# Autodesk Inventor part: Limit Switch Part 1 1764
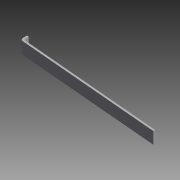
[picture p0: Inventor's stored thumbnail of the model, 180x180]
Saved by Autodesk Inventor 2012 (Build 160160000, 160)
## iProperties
Shininess: 0.0
Created: 2002-01
Part Number: Limit Switch Part 1 1764
Document SubType Name: Modeling
Density: 2.71 g/cm^3
Material: Aluminum-6061
Mass: 0.379544 g
Surface Area: 5.13202 cm^2
Volume: 0.140053 cm^3
Density: 0.0
Volumn: 0.0
Area: 0.0
PropertySet Name: Model Information
Control State: 0
Master: False
Checked Out: False
Author: Administrator
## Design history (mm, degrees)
node "Base1"
body "Solid1"
